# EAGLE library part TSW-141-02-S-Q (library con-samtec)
THROUGH-HOLE .025" SQ POST HEADER Source: Samtec TSW.pdf
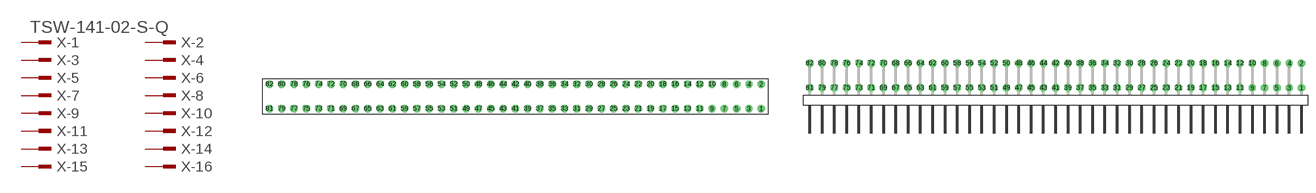
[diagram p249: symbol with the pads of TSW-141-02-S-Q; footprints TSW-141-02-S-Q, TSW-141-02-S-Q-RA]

Designator prefix X; gates -1=MPINV -2=MPIN -3=MPIN -4=MPIN -5=MPIN -6=MPIN -7=MPIN -8=MPIN -9=MPIN -10=MPIN -11=MPIN -12=MPIN -13=MPIN -14=MPIN -15=MPIN -16=MPIN -17=MPIN -18=MPIN -19=MPIN -20=MPIN -21=MPIN -22=MPIN -23=MPIN -24=MPIN -25=MPIN -26=MPIN -27=MPIN -28=MPIN -29=MPIN -30=MPIN -31=MPIN -32=MPIN -33=MPIN -34=MPIN -35=MPIN -36=MPIN -37=MPIN -38=MPIN -39=MPIN -40=MPIN -41=MPIN -42=MPIN -43=MPIN -44=MPIN -45=MPIN -46=MPIN -47=MPIN -48=MPIN -49=MPIN -50=MPIN -51=MPIN -52=MPIN -53=MPIN -54=MPIN -55=MPIN -56=MPIN -57=MPIN -58=MPIN -59=MPIN -60=MPIN -61=MPIN -62=MPIN -63=MPIN -64=MPIN -65=MPIN -66=MPIN -67=MPIN -68=MPIN -69=MPIN -70=MPIN -71=MPIN -72=MPIN -73=MPIN -74=MPIN -75=MPIN -76=MPIN -77=MPIN -78=MPIN -79=MPIN -80=MPIN -81=MPIN -82=MPIN

## TSW-141-02-S-Q (OC_FARNELL: unknown; OC_NEWARK: unknown)  [TSW-141-02-S-Q]
1  -1:1  pas
2  -2:1  pas
3  -3:1  pas
4  -4:1  pas
5  -5:1  pas
6  -6:1  pas
7  -7:1  pas
8  -8:1  pas
9  -9:1  pas
10  -10:1  pas
11  -11:1  pas
12  -12:1  pas
13  -13:1  pas
14  -14:1  pas
15  -15:1  pas
16  -16:1  pas
17  -17:1  pas
18  -18:1  pas
19  -19:1  pas
20  -20:1  pas
21  -21:1  pas
22  -22:1  pas
23  -23:1  pas
24  -24:1  pas
25  -25:1  pas
26  -26:1  pas
27  -27:1  pas
28  -28:1  pas
29  -29:1  pas
30  -30:1  pas
31  -31:1  pas
32  -32:1  pas
33  -33:1  pas
34  -34:1  pas
35  -35:1  pas
36  -36:1  pas
37  -37:1  pas
38  -38:1  pas
39  -39:1  pas
40  -40:1  pas
41  -41:1  pas
42  -42:1  pas
43  -43:1  pas
44  -44:1  pas
45  -45:1  pas
46  -46:1  pas
47  -47:1  pas
48  -48:1  pas
49  -49:1  pas
50  -50:1  pas
51  -51:1  pas
52  -52:1  pas
53  -53:1  pas
54  -54:1  pas
55  -55:1  pas
56  -56:1  pas
57  -57:1  pas
58  -58:1  pas
59  -59:1  pas
60  -60:1  pas
61  -61:1  pas
62  -62:1  pas
63  -63:1  pas
64  -64:1  pas
65  -65:1  pas
66  -66:1  pas
67  -67:1  pas
68  -68:1  pas
69  -69:1  pas
70  -70:1  pas
71  -71:1  pas
72  -72:1  pas
73  -73:1  pas
74  -74:1  pas
75  -75:1  pas
76  -76:1  pas
77  -77:1  pas
78  -78:1  pas
79  -79:1  pas
80  -80:1  pas
81  -81:1  pas
82  -82:1  pas

## TSW-141-02-S-Q-RA (OC_FARNELL: unknown; OC_NEWARK: unknown)  [TSW-141-02-S-Q-RA]
Pads as for TSW-141-02-S-Q

## Footprint TSW-141-02-S-Q (pad centres in mm)
THROUGH-HOLE .025" SQ POST HEADER Source: Samtec TSW.pdf
drill 1 pad 1.5 octagon: 1 50.8,-2.54; 2 50.8,2.54; 3 48.26,-2.54; 4 48.26,2.54; 5 45.72,-2.54; 6 45.72,2.54; 7 43.18,-2.54; 8 43.18,2.54; 9 40.64,-2.54; 10 40.64,2.54; 11 38.1,-2.54; 12 38.1,2.54; 13 35.56,-2.54; 14 35.56,2.54; 15 33.02,-2.54; 16 33.02,2.54; 17 30.48,-2.54; 18 30.48,2.54; 19 27.94,-2.54; 20 27.94,2.54; 21 25.4,-2.54; 22 25.4,2.54; 23 22.86,-2.54; 24 22.86,2.54; 25 20.32,-2.54; 26 20.32,2.54; 27 17.78,-2.54; 28 17.78,2.54; 29 15.24,-2.54; 30 15.24,2.54; 31 12.7,-2.54; 32 12.7,2.54; 33 10.16,-2.54; 34 10.16,2.54; 35 7.62,-2.54; 36 7.62,2.54; 37 5.08,-2.54; 38 5.08,2.54; 39 2.54,-2.54; 40 2.54,2.54; 41 0,-2.54; 42 0,2.54; 43 -2.54,-2.54; 44 -2.54,2.54; 45 -5.08,-2.54; 46 -5.08,2.54; 47 -7.62,-2.54; 48 -7.62,2.54; 49 -10.16,-2.54; 50 -10.16,2.54; 51 -12.7,-2.54; 52 -12.7,2.54; 53 -15.24,-2.54; 54 -15.24,2.54; 55 -17.78,-2.54; 56 -17.78,2.54; 57 -20.32,-2.54; 58 -20.32,2.54; 59 -22.86,-2.54; 60 -22.86,2.54; 61 -25.4,-2.54; 62 -25.4,2.54; 63 -27.94,-2.54; 64 -27.94,2.54; 65 -30.48,-2.54; 66 -30.48,2.54; 67 -33.02,-2.54; 68 -33.02,2.54; 69 -35.56,-2.54; 70 -35.56,2.54; 71 -38.1,-2.54; 72 -38.1,2.54; 73 -40.64,-2.54; 74 -40.64,2.54; 75 -43.18,-2.54; 76 -43.18,2.54; 77 -45.72,-2.54; 78 -45.72,2.54; 79 -48.26,-2.54; 80 -48.26,2.54; 81 -50.8,-2.54; 82 -50.8,2.54

## Footprint TSW-141-02-S-Q-RA (pad centres in mm)
THROUGH-HOLE .025" SQ POST HEADER Source: Samtec TSW.pdf
drill 1 pad 1.5 octagon: 1 50.8,1.524; 2 50.8,6.604; 3 48.26,1.524; 4 48.26,6.604; 5 45.72,1.524; 6 45.72,6.604; 7 43.18,1.524; 8 43.18,6.604; 9 40.64,1.524; 10 40.64,6.604; 11 38.1,1.524; 12 38.1,6.604; 13 35.56,1.524; 14 35.56,6.604; 15 33.02,1.524; 16 33.02,6.604; 17 30.48,1.524; 18 30.48,6.604; 19 27.94,1.524; 20 27.94,6.604; 21 25.4,1.524; 22 25.4,6.604; 23 22.86,1.524; 24 22.86,6.604; 25 20.32,1.524; 26 20.32,6.604; 27 17.78,1.524; 28 17.78,6.604; 29 15.24,1.524; 30 15.24,6.604; 31 12.7,1.524; 32 12.7,6.604; 33 10.16,1.524; 34 10.16,6.604; 35 7.62,1.524; 36 7.62,6.604; 37 5.08,1.524; 38 5.08,6.604; 39 2.54,1.524; 40 2.54,6.604; 41 0,1.524; 42 0,6.604; 43 -2.54,1.524; 44 -2.54,6.604; 45 -5.08,1.524; 46 -5.08,6.604; 47 -7.62,1.524; 48 -7.62,6.604; 49 -10.16,1.524; 50 -10.16,6.604; 51 -12.7,1.524; 52 -12.7,6.604; 53 -15.24,1.524; 54 -15.24,6.604; 55 -17.78,1.524; 56 -17.78,6.604; 57 -20.32,1.524; 58 -20.32,6.604; 59 -22.86,1.524; 60 -22.86,6.604; 61 -25.4,1.524; 62 -25.4,6.604; 63 -27.94,1.524; 64 -27.94,6.604; 65 -30.48,1.524; 66 -30.48,6.604; 67 -33.02,1.524; 68 -33.02,6.604; 69 -35.56,1.524; 70 -35.56,6.604; 71 -38.1,1.524; 72 -38.1,6.604; 73 -40.64,1.524; 74 -40.64,6.604; 75 -43.18,1.524; 76 -43.18,6.604; 77 -45.72,1.524; 78 -45.72,6.604; 79 -48.26,1.524; 80 -48.26,6.604; 81 -50.8,1.524; 82 -50.8,6.604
